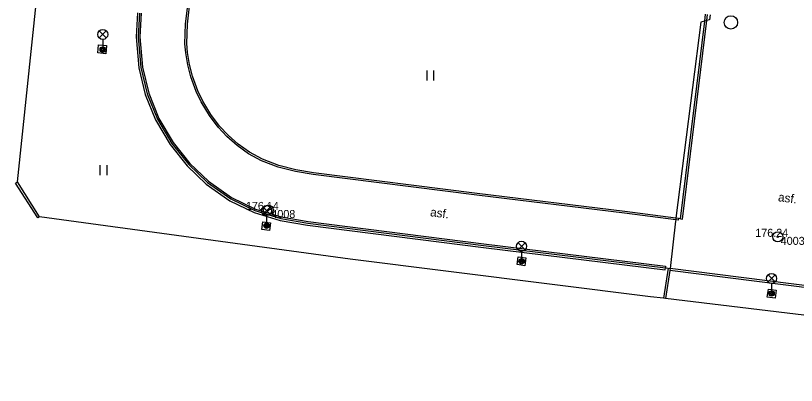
# Model space of a CAD drawing. Extents: x -540235 to -537963, y -1184915 to -1183660.
# Drawn here: x -540189.2 to -540131, y -1184067.2 to -1184039.7 of the extents above; entities that cross this region are included whole.
import ezdxf

# ---------------------------------------------------------------- set-up
doc = ezdxf.new("R2010")
doc.units = 0
for name, color, linetype in [('Vrstva 10', 7, 'Continuous'), ('Vrstva 11', 7, 'Continuous'), ('Vrstva 21', 7, 'Continuous'), ('Vrstva 22', 7, 'Continuous'), ('Vrstva 23', 7, 'Continuous'), ('Vrstva 27', 7, 'Continuous'), ('Vrstva 33', 7, 'Continuous'), ('Vrstva 36', 7, 'Continuous'), ('Vrstva 40', 7, 'Continuous'), ('Vrstva 7', 7, 'Continuous'), ('Vrstva 8', 7, 'Continuous')]:
    doc.layers.add(name, color=color, linetype=linetype)

msp = doc.modelspace()

# ---------------------------------------------------------------- linework, layer by layer
at = {"layer": 'Vrstva 10'}
for p, q in [((-540176.41, -1184040.28), (-540174.92, -1184028.17)), ((-540139.489, -1184054.808), (-540137.677, -1184040.019)), ((-540137.677, -1184040.019), (-540137.622, -1184039.573)), ((-540154.8, -1184052.9), (-540167.01, -1184051.36)), ((-540173.17, -1184053.31), (-540171.38, -1184054.173)), ((-540143.8, -1184054.25), (-540154.8, -1184052.9)), ((-540167.43, -1184055.12), (-540154.32, -1184056.77)), ((-540139.638, -1184054.79), (-540139.489, -1184054.808)), ((-540154.32, -1184056.77), (-540140.77, -1184058.44)), ((-540140.77, -1184058.44), (-540140.558, -1184058.472)), ((-540111.5, -1184062.145), (-540140.41, -1184058.495))]:
    msp.add_line(p, q, dxfattribs=at)
for points in [[(-540179.98, -1184039.46), (-540180.085, -1184041.238), (-540179.88, -1184043.51), (-540179.4, -1184045.472), (-540178.64, -1184047.36)], [(-540174.66, -1184047.03), (-540175.267, -1184046.017), (-540175.624, -1184045.266), (-540176.023, -1184044.172), (-540176.25, -1184043.3), (-540176.404, -1184042.399), (-540176.461, -1184041.741), (-540176.41, -1184040.28)], [(-540167.01, -1184051.36), (-540168.322, -1184051.146), (-540169.598, -1184050.818), (-540170.817, -1184050.346), (-540171.77, -1184049.83), (-540172.624, -1184049.226), (-540173.376, -1184048.562), (-540174.01, -1184047.882), (-540174.66, -1184047.03)], [(-540178.64, -1184047.36), (-540177.57, -1184049.17), (-540176.31, -1184050.74), (-540174.91, -1184052.082), (-540173.17, -1184053.31)], [(-540171.38, -1184054.173), (-540169.45, -1184054.77), (-540167.43, -1184055.12)], [(-540139.638, -1184054.79), (-540139.8, -1184054.77), (-540139.981, -1184054.747), (-540143.8, -1184054.25)]]:
    msp.add_lwpolyline(points, dxfattribs=at)
at = {"layer": 'Vrstva 11'}
for p, q in [((-540176.54, -1184040.27), (-540175.047, -1184028.141)), ((-540139.638, -1184054.79), (-540137.833, -1184040.063)), ((-540137.833, -1184040.063), (-540137.77, -1184039.55)), ((-540154.816, -1184053.029), (-540167.029, -1184051.489)), ((-540173.246, -1184053.44), (-540171.435, -1184054.313)), ((-540173.108, -1184053.205), (-540171.335, -1184054.06)), ((-540143.816, -1184054.379), (-540154.816, -1184053.029)), ((-540167.412, -1184055), (-540154.305, -1184056.649)), ((-540167.452, -1184055.268), (-540154.339, -1184056.919)), ((-540154.339, -1184056.919), (-540140.79, -1184058.589)), ((-540154.305, -1184056.649), (-540140.754, -1184058.32)), ((-540140.79, -1184058.589), (-540140.77, -1184058.44)), ((-540140.754, -1184058.32), (-540140.77, -1184058.44)), ((-540111.517, -1184062.294), (-540140.429, -1184058.644))]:
    msp.add_line(p, q, dxfattribs=at)
for points in [[(-540180.129, -1184039.446), (-540180.235, -1184041.24), (-540180.028, -1184043.535), (-540179.543, -1184045.518), (-540178.775, -1184047.427)], [(-540179.859, -1184039.471), (-540179.963, -1184041.236), (-540179.76, -1184043.49), (-540179.284, -1184045.435), (-540178.531, -1184047.306)], [(-540174.768, -1184047.103), (-540175.382, -1184046.079), (-540175.744, -1184045.316), (-540176.147, -1184044.21), (-540176.377, -1184043.327), (-540176.533, -1184042.416), (-540176.592, -1184041.745), (-540176.54, -1184040.27)], [(-540183.03, -1184041.83), (-540182.43, -1184041.89), (-540182.49, -1184042.49), (-540183.09, -1184042.43), (-540183.03, -1184041.83)], [(-540178.775, -1184047.427), (-540177.694, -1184049.255), (-540176.421, -1184050.842), (-540175.005, -1184052.198), (-540173.246, -1184053.44)], [(-540178.531, -1184047.306), (-540177.47, -1184049.101), (-540176.22, -1184050.658), (-540174.832, -1184051.988), (-540173.108, -1184053.205)], [(-540167.029, -1184051.489), (-540168.348, -1184051.273), (-540169.638, -1184050.942), (-540170.871, -1184050.464), (-540171.839, -1184049.941), (-540172.705, -1184049.328), (-540173.467, -1184048.655), (-540174.11, -1184047.965), (-540174.768, -1184047.103)], [(-540171.435, -1184054.313), (-540169.485, -1184054.916), (-540167.452, -1184055.268)], [(-540171.335, -1184054.06), (-540169.422, -1184054.652), (-540167.412, -1184055)], [(-540139.8, -1184054.77), (-540139.817, -1184054.899), (-540139.997, -1184054.876), (-540143.816, -1184054.379)], [(-540170.78, -1184055.01), (-540170.2, -1184055.09), (-540170.28, -1184055.67), (-540170.86, -1184055.59), (-540170.78, -1184055.01)], [(-540151.74, -1184057.62), (-540151.16, -1184057.7), (-540151.24, -1184058.28), (-540151.82, -1184058.2), (-540151.74, -1184057.62)], [(-540133.09, -1184060.02), (-540132.495, -1184060.099), (-540132.575, -1184060.694), (-540133.169, -1184060.615), (-540133.09, -1184060.02)]]:
    msp.add_lwpolyline(points, dxfattribs=at)
at = {"layer": 'Vrstva 21'}
for centre, radius in [((-540170.37, -1184054.13), 0.375), ((-540170.37, -1184054.13), 0.05), ((-540132.39, -1184056.13), 0.375), ((-540132.39, -1184056.13), 0.05)]:
    msp.add_circle(centre, radius, dxfattribs=at)
at = {"layer": 'Vrstva 27'}
msp.add_circle((-540135.88, -1184040.16), 0.5, dxfattribs=at)
at = {"layer": 'Vrstva 33'}
for p, q in [((-540182.985, -1184041.32), (-540182.455, -1184040.79)), ((-540182.985, -1184040.79), (-540182.455, -1184041.32)), ((-540182.72, -1184041.43), (-540182.72, -1184042.18)), ((-540170.765, -1184054.44), (-540170.235, -1184053.91)), ((-540170.765, -1184053.91), (-540170.235, -1184054.44)), ((-540170.5, -1184054.55), (-540170.5, -1184055.3)), ((-540151.755, -1184057.1), (-540151.225, -1184056.57)), ((-540151.755, -1184056.57), (-540151.225, -1184057.1)), ((-540151.49, -1184057.21), (-540151.49, -1184057.96)), ((-540133.115, -1184059.49), (-540132.585, -1184058.96)), ((-540133.115, -1184058.96), (-540132.585, -1184059.49)), ((-540132.85, -1184059.6), (-540132.85, -1184060.35))]:
    msp.add_line(p, q, dxfattribs=at)
for centre, radius in [((-540182.72, -1184041.055), 0.375), ((-540182.72, -1184042.18), 0.2), ((-540182.72, -1184042.18), 0.1445), ((-540182.72, -1184042.18), 0.0876), ((-540170.5, -1184054.175), 0.375), ((-540170.5, -1184055.3), 0.2), ((-540170.5, -1184055.3), 0.1445), ((-540170.5, -1184055.3), 0.0876), ((-540151.49, -1184056.835), 0.375), ((-540151.49, -1184057.96), 0.2), ((-540151.49, -1184057.96), 0.1445), ((-540151.49, -1184057.96), 0.0876), ((-540132.85, -1184059.225), 0.375), ((-540132.85, -1184060.35), 0.2), ((-540132.85, -1184060.35), 0.1445), ((-540132.85, -1184060.35), 0.0876)]:
    msp.add_circle(centre, radius, dxfattribs=at)
at = {"layer": 'Vrstva 36'}
for p, q in [((-540158.539, -1184044.485), (-540158.539, -1184043.735)), ((-540158.039, -1184044.485), (-540158.039, -1184043.735)), ((-540182.899, -1184051.547), (-540182.899, -1184050.797)), ((-540182.399, -1184051.547), (-540182.399, -1184050.797))]:
    msp.add_line(p, q, dxfattribs=at)
at = {"layer": 'Vrstva 7'}
for p, q in [((-540189.08, -1184052.04), (-540187.346, -1184035.611)), ((-540137.425, -1184039.604), (-540137.467, -1184039.959)), ((-540138.127, -1184040.147), (-540139.981, -1184054.747)), ((-540187.43, -1184054.63), (-540189.08, -1184052.04)), ((-540164.27, -1184057.799), (-540187.43, -1184054.63)), ((-540141.88, -1184060.609), (-540164.27, -1184057.799)), ((-540140.558, -1184058.472), (-540140.898, -1184060.692)), ((-540140.898, -1184060.692), (-540141.88, -1184060.609)), ((-540087.769, -1184067.192), (-540140.75, -1184060.715))]:
    msp.add_line(p, q, dxfattribs=at)
for points in [[(-540137.467, -1184039.959), (-540137.677, -1184040.019), (-540137.833, -1184040.063), (-540138.127, -1184040.147)], [(-540187.43, -1184054.63), (-540187.565, -1184054.716), (-540189.215, -1184052.126), (-540189.08, -1184052.04)], [(-540139.981, -1184054.747), (-540139.997, -1184054.876), (-540140.01, -1184054.975)], [(-540140.558, -1184058.472), (-540140.41, -1184058.495), (-540140.429, -1184058.644), (-540140.75, -1184060.715), (-540140.898, -1184060.692)]]:
    msp.add_lwpolyline(points, dxfattribs=at)
at = {"layer": 'Vrstva 8'}
msp.add_line((-540140.01, -1184054.975), (-540140.41, -1184058.495), dxfattribs=at)

# ---------------------------------------------------------------- texts
at = {"layer": 'Vrstva 22'}
for s, p in [('176.14', (-540172.045, -1184054.13)), ('176.24', (-540134.065, -1184056.13))]:
    msp.add_text(s, height=0.6, dxfattribs=at).set_placement(p)
at = {"layer": 'Vrstva 23'}
for s, p in [(' 4008', (-540170.37, -1184054.73)), (' 4003', (-540132.39, -1184056.73))]:
    msp.add_text(s, height=0.6, dxfattribs=at).set_placement(p)
at = {"layer": 'Vrstva 40'}
for rotation, p in [(352.804256, (-540132.39, -1184053.475)), (352.826578, (-540158.332, -1184054.59))]:
    msp.add_text('asf.', height=0.65, rotation=rotation, dxfattribs=at).set_placement(p)

doc.saveas('drawing.dxf')
